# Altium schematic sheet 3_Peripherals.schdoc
size 309 x 223 mm; Symbol: Sheet-Symbol_A4; Device: Sheet-Symbol_A4; @Project Name: Digital_Watch_V01; @Page Count: 3; @Update Date: 2024-12-20; @Create Date: 2024-12-19; @Schematic Name: D-Watch_Sch_v1.4; @Page No: 3; @Page Name: Peripherals; Company: EasyEDA.com; Reviewed: EasyEDA; Version: V0.1; Page Size: A4; Part Number: JLCPCB-002; Drawn: EasyEDA; @Board Name: D-Watch_Board_v1.4; @Create Time: 19:17:03; @Update Time: 21:18:03
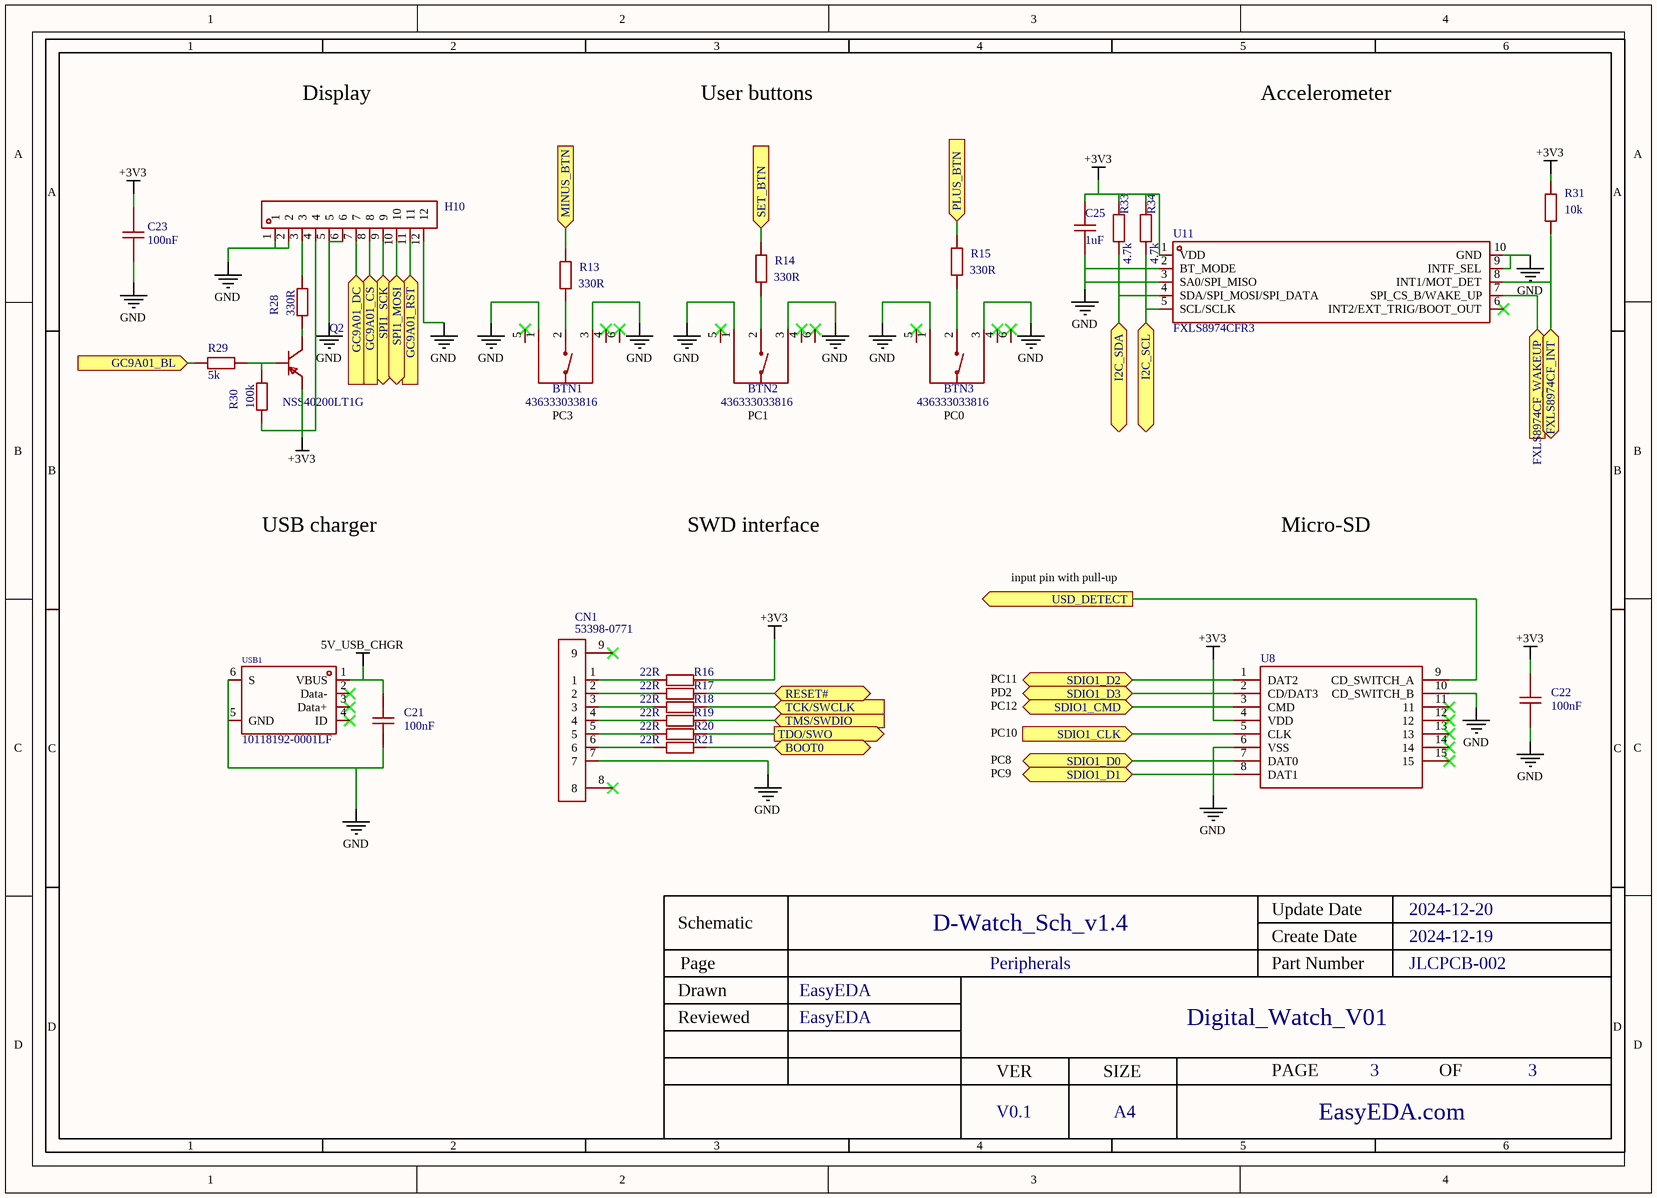
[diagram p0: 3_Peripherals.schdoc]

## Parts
BTN1  436333033816  [SW-SMD_436333033816]  (value not drawn)
BTN2  436333033816  [SW-SMD_436333033816]  (value not drawn)
BTN3  436333033816  [SW-SMD_436333033816]  (value not drawn)
C21  100nF  [C0603]  (value not drawn)
C22  100nF  [C0603]  (value not drawn)
C23  100nF  [C0603]  (value not drawn)
C25  1uF  [C0603]  (value not drawn)
CN1  53398-0771  [CONN-SMD_7P-P1.25_53398-0771]  (value not drawn)
H10  HDR-M_2.54_1x12P  [HDR-TH_12P-P2.54-V-M]  (value not drawn)
Q2  NSS40200LT1G  [SOT-23-3_L2.9-W1.3-P1.90-LS2.4-BR]  (value not drawn)
R13  330R  [R0603]  (value not drawn)
R14  330R  [R0603]  (value not drawn)
R15  330R  [R0603]  (value not drawn)
R16  22R  [R0603]  (value not drawn)
R17  22R  [R0603]  (value not drawn)
R18  22R  [R0603]  (value not drawn)
R19  22R  [R0603]  (value not drawn)
R20  22R  [R0603]  (value not drawn)
R21  22R  [R0603]  (value not drawn)
R28  330R  [R0603]  (value not drawn)
R29  5k  [R0603]  (value not drawn)
R30  100k  [R0603]  (value not drawn)
R31  10k  [R0603]  (value not drawn)
R33  4.7k  [R0603]  (value not drawn)
R34  4.7k  [R0603]  (value not drawn)
U8  DM3BT-DSF-PEJS_  [DM3BTDSFPEJS]  (value not drawn)
U11  FXLS8974CFR3  [DFN-10_L2.0-W2.0-P0.40-BL]  (value not drawn)
USB1  10118192-0001LF  [MICRO-USB-SMD_10118192-0001LF_1]  (value not drawn)

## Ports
BOOT0 (bidir), FXLS8974CF_INT (bidir), FXLS8974CF_WAKEUP (in), GC9A01_BL (in), GC9A01_CS (in), GC9A01_DC (in), GC9A01_RST (in), I2C_SCL (bidir), I2C_SDA (bidir), MINUS_BTN (in), PLUS_BTN (in), RESET# (bidir), SDIO1_CLK (in), SDIO1_CMD (bidir), SDIO1_D0 (bidir), SDIO1_D1 (bidir), SDIO1_D2 (bidir), SDIO1_D3 (bidir), SET_BTN (in), SPI1_MOSI (bidir), SPI1_SCK (bidir), TCK/SWCLK (in), TDO/SWO (out), TMS/SWDIO (in), USD_DETECT (out)

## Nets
5V_USB_CHGR: C21.1 USB1.1(VBUS)
+3V3: C22.1 C23.1 C25.2 H10.4 Q2.2(E) R16.1 R30.1 R31.2 R33.2 R34.2 U8.4(VDD) U11.1(VDD)
GND: BTN1.1 BTN1.3 BTN2.1 BTN2.3 BTN3.1 BTN3.3 C21.2 C22.2 C23.2 C25.1 CN1.7 H10.1 H10.2 H10.5 H10.6 H10.12 U8.6(VSS) U8.10(CD_SWITCH_B) U11.2(BT_MODE) U11.3(SA0/SPI_MISO) U11.9(INTF_SEL) U11.10(GND) USB1.5(GND) USB1.6(S)
BOOT0: R21.1 ; port BOOT0
FXLS8974CF_INT: R31.1 U11.8(INT1/MOT_DET) ; port FXLS8974CF_INT
FXLS8974CF_WAKEUP: U11.7(SPI_CS_B/WAKE_UP) ; port FXLS8974CF_WAKEUP
GC9A01_BL: R29.2 ; port GC9A01_BL
GC9A01_CS: H10.8 ; port GC9A01_CS
GC9A01_DC: H10.7 ; port GC9A01_DC
GC9A01_RST: H10.11 ; port GC9A01_RST
I2C_SCL: R34.1 U11.5(SCL/SCLK) ; port I2C_SCL
I2C_SDA: R33.1 U11.4(SDA/SPI_MOSI/SPI_DATA) ; port I2C_SDA
MINUS_BTN: R13.2 ; port MINUS_BTN
PLUS_BTN: R15.2 ; port PLUS_BTN
RESET#: R17.1 ; port RESET#
SDIO1_CLK: U8.5(CLK) ; port SDIO1_CLK
SDIO1_CMD: U8.3(CMD) ; port SDIO1_CMD
SDIO1_D0: U8.7(DAT0) ; port SDIO1_D0
SDIO1_D1: U8.8(DAT1) ; port SDIO1_D1
SDIO1_D2: U8.1(DAT2) ; port SDIO1_D2
SDIO1_D3: U8.2(CD/DAT3) ; port SDIO1_D3
SET_BTN: R14.2 ; port SET_BTN
SPI1_MOSI: H10.10 ; port SPI1_MOSI
SPI1_SCK: H10.9 ; port SPI1_SCK
TCK/SWCLK: R18.1 ; port TCK/SWCLK
TDO/SWO: R20.1 ; port TDO/SWO
TMS/SWDIO: R19.1 ; port TMS/SWDIO
USD_DETECT: U8.9(CD_SWITCH_A) ; port USD_DETECT
NetBTN1_2: BTN1.2 R13.1
NetBTN2_2: BTN2.2 R14.1
NetBTN3_2: BTN3.2 R15.1
NetCN1_1: CN1.1 R16.2
NetCN1_2: CN1.2 R17.2
NetCN1_3: CN1.3 R18.2
NetCN1_4: CN1.4 R19.2
NetCN1_5: CN1.5 R20.2
NetCN1_6: CN1.6 R21.2
NetH10_3: H10.3 R28.2
NetQ2_1: Q2.1(B) R29.1 R30.2
NetQ2_3: Q2.3(C) R28.1

Not connected (* = marked no-connect by the designer): BTN1 4* 5* 6*; BTN2 4* 5* 6*; BTN3 4* 5* 6*; CN1 8* 9*; U8 11* 12* 13* 14* 15*; U11 6(INT2/EXT_TRIG/BOOT_OUT)*; USB1 2(Data-)* 3(Data+)* 4(ID)*

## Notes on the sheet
- Display
- User buttons
- Accelerometer
- PC3
- PC1
- PC0
- USB charger
- SWD interface
- Micro-SD
- input pin with pull-up
- PC11
- PC10
- PC12
- PD2
- PC8
- PC9

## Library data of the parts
BTN1-BTN3 = 436333033816: Circuit:SPST - normally open Actuator Style:Round Button Operating Force:160gf Mounting Style:Standing paste Contact Current:50mA Voltage Rating (DC):12V Pin Style:SMDSplicing Operating Temperature:-40℃~+85℃ Operating Temperature:-40℃~+85℃; Manufacturer: Wurth(伍尔特); Add into BOM: yes; Operating Force: 160gf; Contact Current: 50mA; Voltage Rating (DC): 12V
C21-C23 = GCJ188R71C104KA01D: Capacitance: Tolerance:±10% Tolerance:±10% Voltage Rated: Temperature Coefficient:; Manufacturer: muRata(村田); Add into BOM: yes; Tolerance: ±10%
C25 = AC0603KRX7R6BB105: Capacitance: Tolerance:±10% Tolerance:±10% Voltage Rated: Temperature Coefficient:; Manufacturer: YAGEO(国巨); Add into BOM: yes; Tolerance: ±10%
CN1 = 53398-0771: Manufacturer: MOLEX; Manufacturer Part: 533980771; Convert to PCB: yes
H10 = HDR-M_2.54_1x12P: Symbol: HDR_2.54-1x12P; Convert to PCB: yes
Q2 = NSS40200LT1G: Transistor Type: Collector Current (Ic): Collector-Emitter Breakdown Voltage (Vceo): Power Dissipation (Pd): DC Current Gain (hFE@Ic,Vce):150@2.0A,2.0V DC Current Gain (hFE@Ic,Vce):150@2.0A,2.0V Transition Frequency (fT):100MHz Collector Cut-Off Current (; Manufacturer: onsemi(安森美); Add into BOM: yes; Transition Frequency (fT): 100MHz; Collector Cut-Off Current (Icbo): 100nA; Collector-Emitter Saturation Voltage (VCE(sat)@Ic,Ib): 0.135V@2.0A,0.200A
R13-R21 R28-R31 R33 R34 = Res_0603: Symbol: Res; Convert to PCB: yes
U8 = DM3BT-DSF-PEJS_: Add into BOM: yes
U11 = FXLS8964AFR3: Manufacturer: NXP(恩智浦); Add into BOM: yes
USB1 = 10118192-0001LF: Connector Type:Micro-B Standard:USB 2.0 Gender:Female Number of Ports:1 Number of Contacts:5P Mounting Style:卧贴 Current Rating - Power (Max):- Operating Temperature Range:-30℃~+80℃ Operating Temperature Range:-30℃~+80℃; Manufacturer: Amphenol; Add into BOM: yes; Gender: Female; Number of Ports: 1; Number of Contacts: 5P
